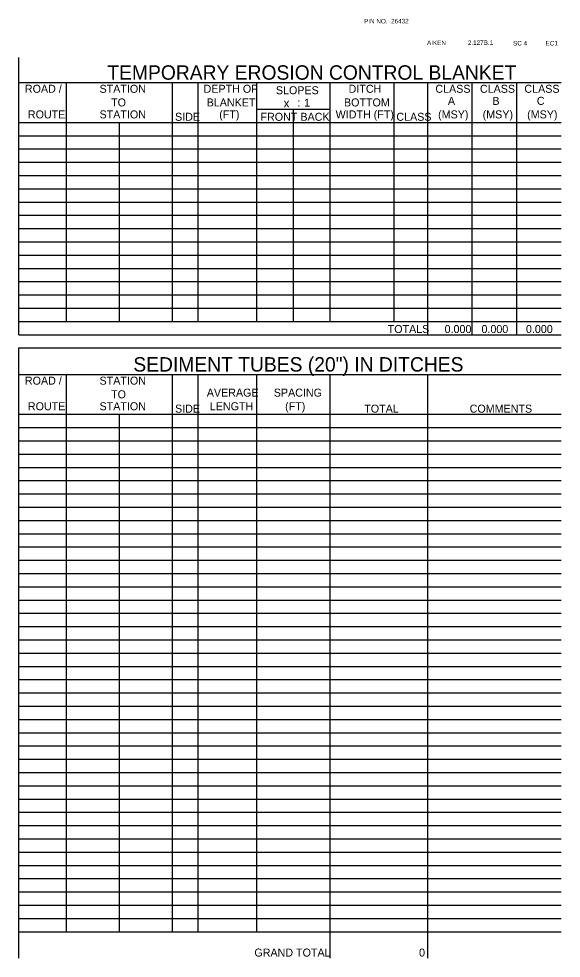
# Model space of a CAD drawing. Extents: x 17139 to 21295, y 12843 to 18076.
# Drawn here: x 20702 to 21295, y 12843 to 13869 of the extents above; entities that cross this region are included whole.
import ezdxf

# ---------------------------------------------------------------- set-up
doc = ezdxf.new("R2010")
doc.units = 0
doc.layers.add('Level 1', color=7, linetype='Continuous')
doc.layers.add('Level 3', color=7, linetype='Continuous')

msp = doc.modelspace()

# ---------------------------------------------------------------- linework, layer by layer
at = {"layer": 'Level 1'}
for p, q in [((20702, 13524.1), (20702, 13826.9)), ((20702, 13799.6), (21294.8, 13799.6)), ((20754.1, 13538.6), (20754.1, 13799.6)), ((20870.1, 13538.6), (20870.1, 13799.6)), ((20898.2, 13538.6), (20898.2, 13799.6)), ((20962.2, 13538.6), (20962.2, 13799.6)), ((21042.4, 13538.6), (21042.4, 13799.6)), ((21112.3, 13538.6), (21112.3, 13799.6)), ((21149, 13524.1), (21149, 13799.6)), ((21197.6, 13524.1), (21197.6, 13799.6)), ((21246.2, 13524.1), (21246.2, 13799.6)), ((20962.2, 13770.6), (21042.4, 13770.6)), ((21002.3, 13538.6), (21002.3, 13770.6)), ((20702, 13756.1), (21294.8, 13756.1)), ((20812.1, 13538.6), (20812.1, 13756.1)), ((21042.4, 13756.1), (21294.8, 13756.1)), ((20702, 13741.6), (21294.8, 13741.6)), ((20702, 13727.1), (21294.8, 13727.1)), ((20702, 13712.6), (21294.8, 13712.6)), ((20702, 13698.1), (21294.8, 13698.1)), ((20702, 13683.6), (21294.8, 13683.6)), ((20702, 13669.1), (21294.8, 13669.1)), ((20702, 13654.6), (21294.8, 13654.6)), ((20702, 13640.1), (21294.8, 13640.1)), ((20702, 13625.6), (21294.8, 13625.6)), ((20702, 13611.1), (21294.8, 13611.1)), ((20702, 13596.6), (21294.8, 13596.6)), ((20702, 13582.1), (21294.8, 13582.1)), ((20702, 13567.6), (21294.8, 13567.6)), ((20702, 13553.1), (21294.8, 13553.1)), ((20702, 13538.6), (21294.8, 13538.6)), ((20702, 13524.1), (21294.8, 13524.1)), ((20702, 12842.6), (20702, 13509.6)), ((20702, 13509.6), (21294.8, 13509.6)), ((20702, 13480.6), (21294.8, 13480.6)), ((20754.1, 12871.6), (20754.1, 13480.6)), ((20870.1, 12871.6), (20870.1, 13480.6)), ((20898.2, 12871.6), (20898.2, 13480.6)), ((20962.2, 12871.6), (20962.2, 13480.6)), ((21042.4, 12842.6), (21042.4, 13480.6)), ((21149, 12842.6), (21149, 13480.6)), ((20702, 13437.1), (21294.8, 13437.1)), ((20812.1, 12871.6), (20812.1, 13437.1)), ((20702, 13422.6), (21294.8, 13422.6)), ((20702, 13408.1), (21294.8, 13408.1)), ((20702, 13393.6), (21294.8, 13393.6)), ((20702, 13379.1), (21294.8, 13379.1)), ((20702, 13364.6), (21294.8, 13364.6)), ((20702, 13350.1), (21294.8, 13350.1)), ((20702, 13335.6), (21294.8, 13335.6)), ((20702, 13321.1), (21294.8, 13321.1)), ((20702, 13306.6), (21294.8, 13306.6)), ((20702, 13292.1), (21294.8, 13292.1)), ((20702, 13277.6), (21294.8, 13277.6)), ((20702, 13263.1), (21294.8, 13263.1)), ((20702, 13248.6), (21294.8, 13248.6)), ((20702, 13234.1), (21294.8, 13234.1)), ((20702, 13219.6), (21294.8, 13219.6)), ((20702, 13205.1), (21294.8, 13205.1)), ((20702, 13190.6), (21294.8, 13190.6)), ((20702, 13176.1), (21294.8, 13176.1)), ((20702, 13161.6), (21294.8, 13161.6)), ((20702, 13147.1), (21294.8, 13147.1)), ((20702, 13132.6), (21294.8, 13132.6)), ((20702, 13118.1), (21294.8, 13118.1)), ((20702, 13103.6), (21294.8, 13103.6)), ((20702, 13089.1), (21294.8, 13089.1)), ((20702, 13074.6), (21294.8, 13074.6)), ((20702, 13060.1), (21294.8, 13060.1)), ((20702, 13045.6), (21294.8, 13045.6)), ((20702, 13031.1), (21294.8, 13031.1)), ((20702, 13016.6), (21294.8, 13016.6)), ((20702, 13002.1), (21294.8, 13002.1)), ((20702, 12987.6), (21294.8, 12987.6)), ((20702, 12973.1), (21294.8, 12973.1)), ((20702, 12958.6), (21294.8, 12958.6)), ((20702, 12944.1), (21294.8, 12944.1)), ((20702, 12929.6), (21294.8, 12929.6)), ((20702, 12915.1), (21294.8, 12915.1)), ((20702, 12900.6), (21294.8, 12900.6)), ((20702, 12886.1), (21294.8, 12886.1)), ((20702, 12871.6), (21294.8, 12871.6))]:
    msp.add_line(p, q, dxfattribs=at)

# ---------------------------------------------------------------- texts
for s, height, p in [('TEMPORARY EROSION CONTROL BLANKET', 15.747, (20798.8, 13802.8)), ('ROAD /', 8.75, (20708.7, 13788.5)), ('STATION', 8.75, (20790.3, 13788.5)), ('DEPTH OF', 8.75, (20904, 13788.5)), ('SLOPES', 8.75, (20983, 13786.9)), ('DITCH', 8.75, (21062.5, 13788.5)), ('CLASS', 8.75, (21157.3, 13788.5)), ('CLASS', 8.75, (21206, 13788.5)), ('CLASS', 8.75, (21254.6, 13788.5)), ('TO ', 8.75, (20802.9, 13773.6)), ('BLANKET', 8.75, (20907.4, 13773.6)), ('x ', 9.62, (20991.4, 13772.5)), (':', 8.75, (21006.3, 13773.4)), (' 1', 8.75, (21010.6, 13773.4)), ('BOTTOM', 8.75, (21057.4, 13773.6)), ('A', 8.75, (21171, 13775.3)), ('B', 8.75, (21219.6, 13775.3)), ('C', 8.75, (21268.2, 13775.3)), ('ROUTE', 8.75, (20712, 13760.5)), ('STATION', 8.75, (20790.3, 13760.5)), ('(FT)', 8.75, (20921.1, 13760.5)), ('WIDTH (FT)', 8.75, (21048.3, 13760.5)), ('(MSY)', 8.75, (21160.3, 13760.5)), ('(MSY)', 8.75, (21209, 13760.5)), ('(MSY)', 8.75, (21257.6, 13760.5)), ('SIDE', 8.75, (20872.8, 13757.9)), ('FRONT', 8.75, (20966.2, 13757.9)), ('BACK', 8.75, (21009.8, 13757.9)), ('CLASS', 8.75, (21114.7, 13757.9)), ('TOTALS', 8.75, (21105.2, 13525.9)), ('0.000', 8.75, (21167.4, 13525.9)), ('0.000', 8.75, (21207.7, 13525.9)), ('0.000', 8.75, (21256.3, 13525.9)), ('SEDIMENT TUBES (20") IN DITCHES', 15.747, (20827.2, 13483.8)), ('ROAD /', 8.75, (20708.7, 13469.5)), ('STATION', 8.75, (20790.3, 13469.5)), ('TO ', 8.75, (20802.9, 13454.6)), ('AVERAGE', 8.75, (20907.5, 13456.4)), ('SPACING', 8.75, (20980.7, 13456.4)), ('ROUTE', 8.75, (20712, 13441.5)), ('STATION', 8.75, (20790.3, 13441.5)), ('SIDE', 8.75, (20872.8, 13438.9)), ('LENGTH', 8.75, (20910.8, 13441.5)), ('(FT)', 8.75, (20993.1, 13441.5)), ('TOTAL', 8.75, (21079.6, 13438.9)), ('COMMENTS', 8.75, (21194.8, 13438.9)), (' GRAND TOTAL', 8.748, (20956.3, 12844.4)), ('0', 8.75, (21139.5, 12844.4))]:
    msp.add_text(s, height=height, dxfattribs=at).set_placement(p)
at = {"layer": 'Level 3'}
for s, p in [('PIN NO.  26432', (21079.4, 13864.3)), ('AIKEN', (21148.2, 13840.6)), (' 2.127B.1', (21190.9, 13840.8)), ('SC 4', (21242.2, 13840.2)), ('EC1', (21277.8, 13840.2))]:
    msp.add_text(s, height=5, dxfattribs=at).set_placement(p)

doc.saveas('drawing.dxf')
